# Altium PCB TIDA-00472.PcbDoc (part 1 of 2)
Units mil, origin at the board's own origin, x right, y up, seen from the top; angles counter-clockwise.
Board outline 3661.41 x 4133.85 mil, 2 copper layers (Top Layer, Bottom Layer), stack 62 mil thick; 187 components, 96 nets, 460 pads, 195 vias.
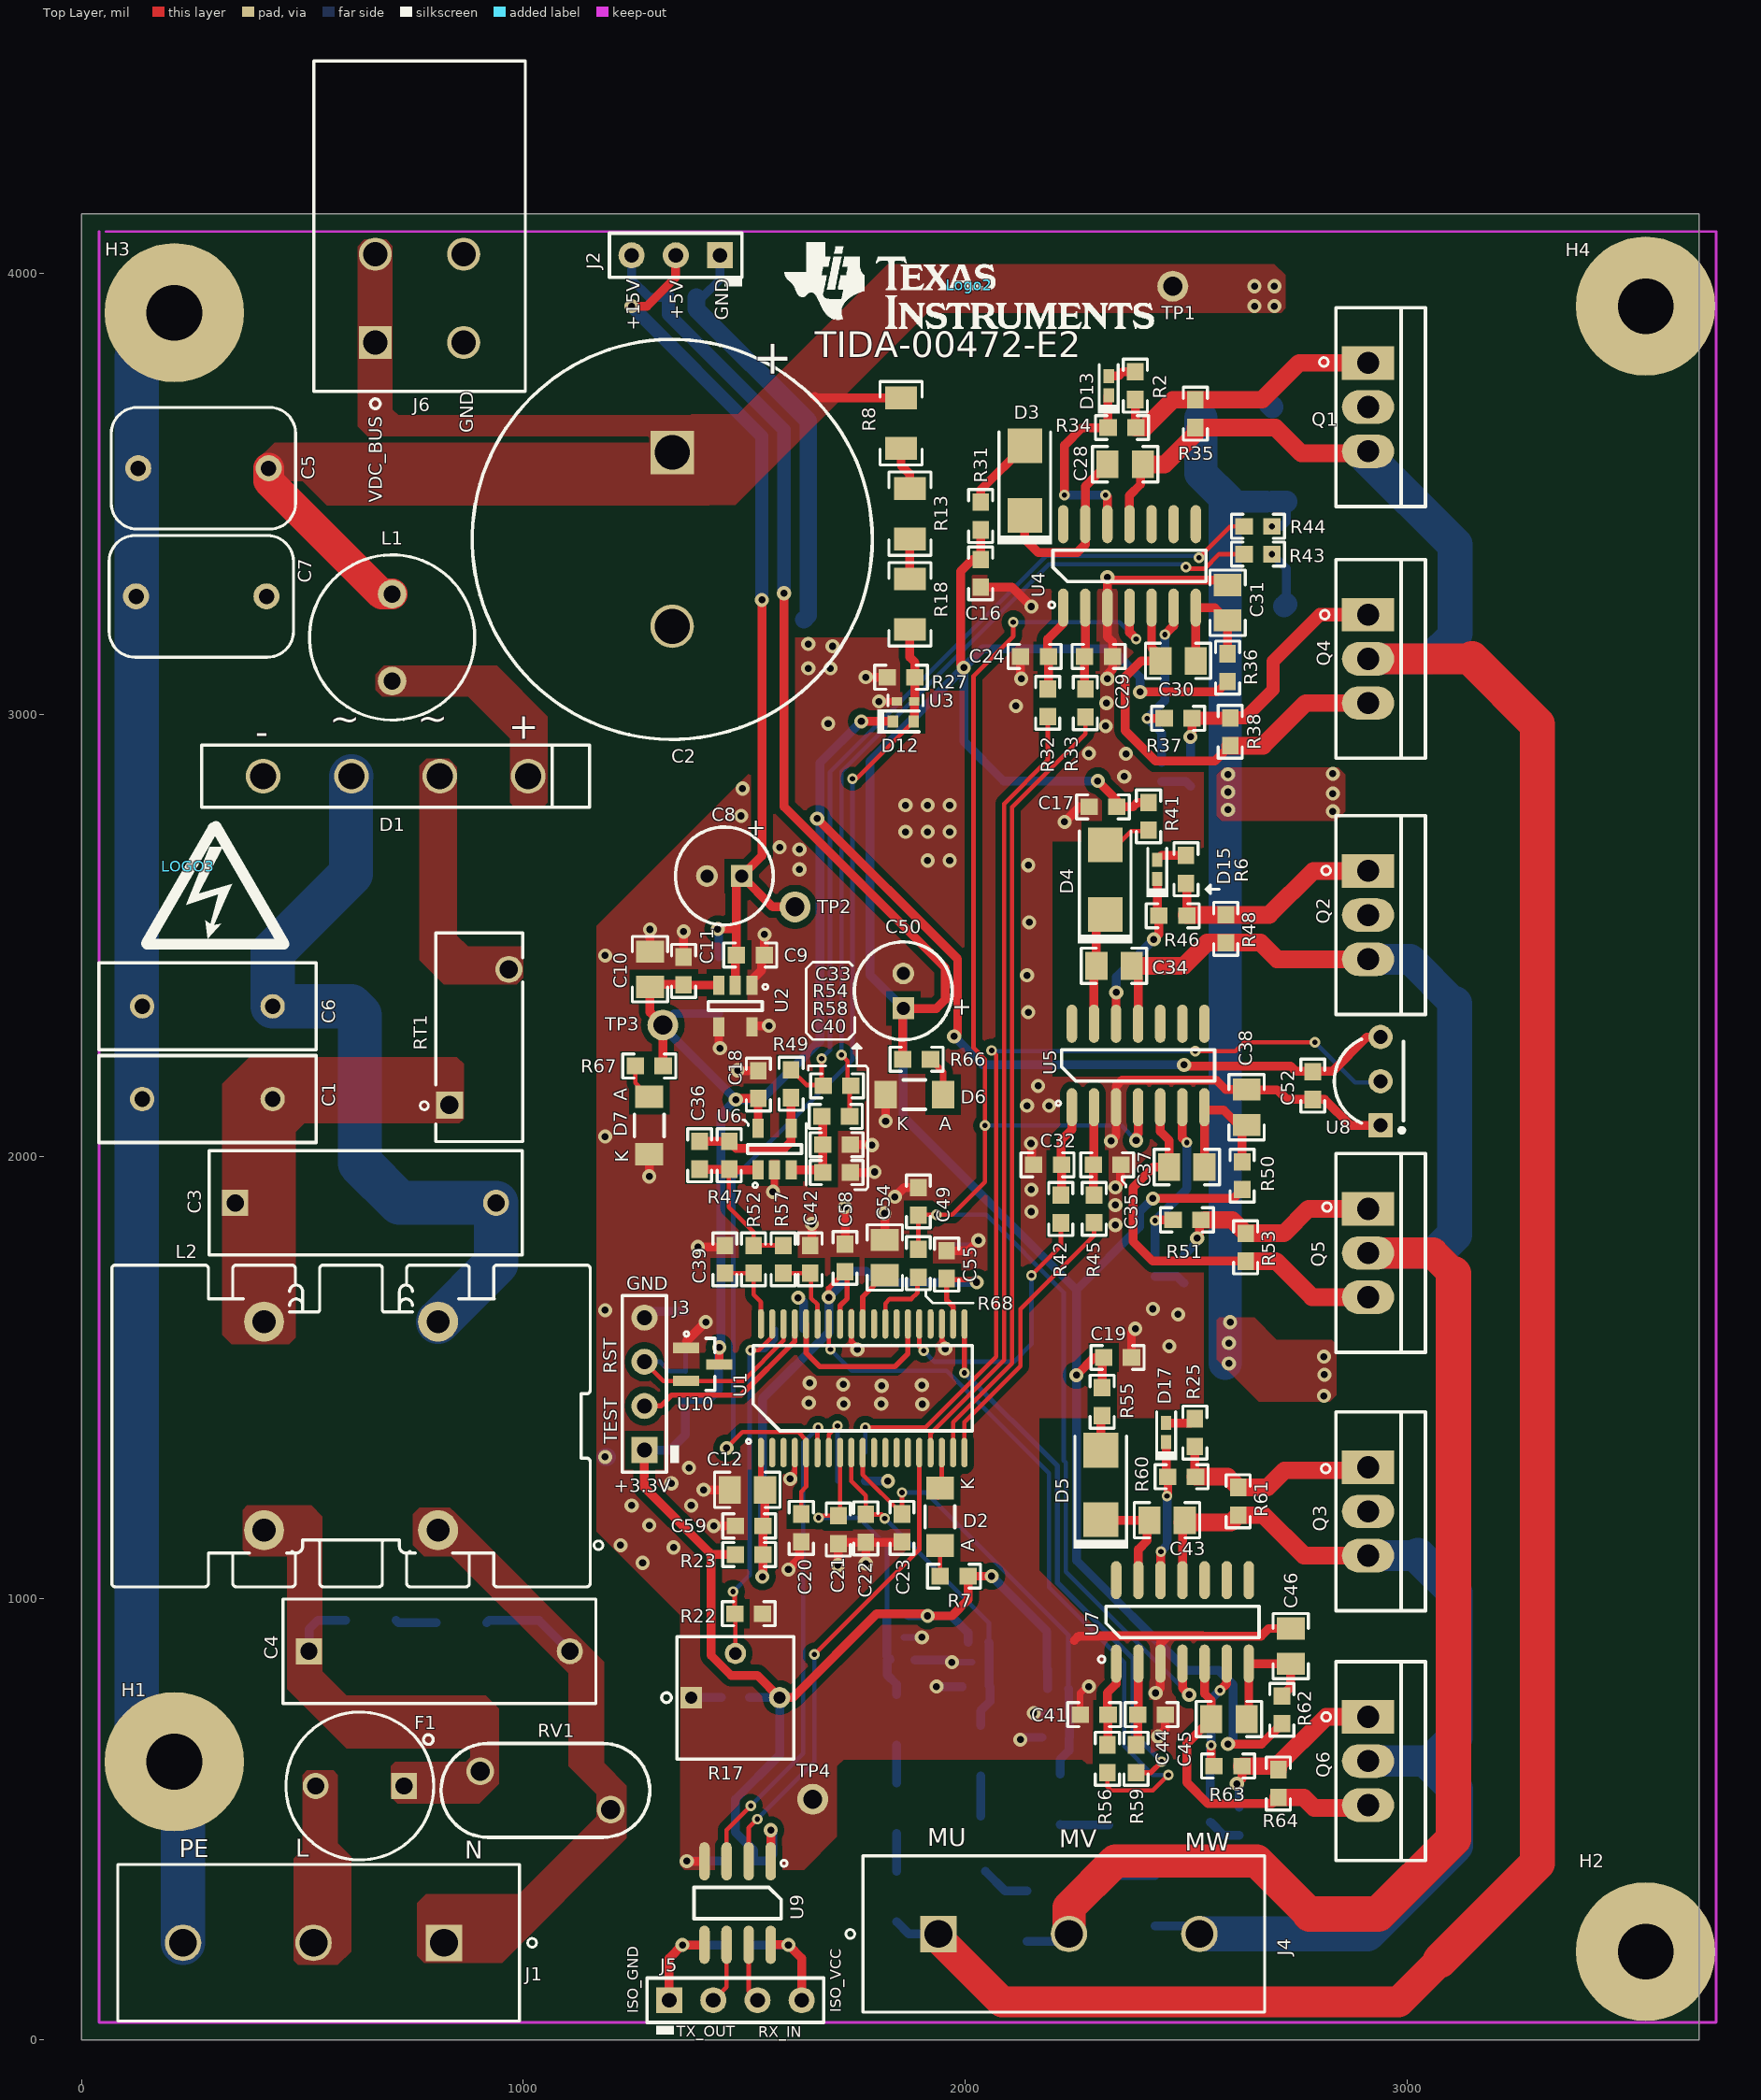
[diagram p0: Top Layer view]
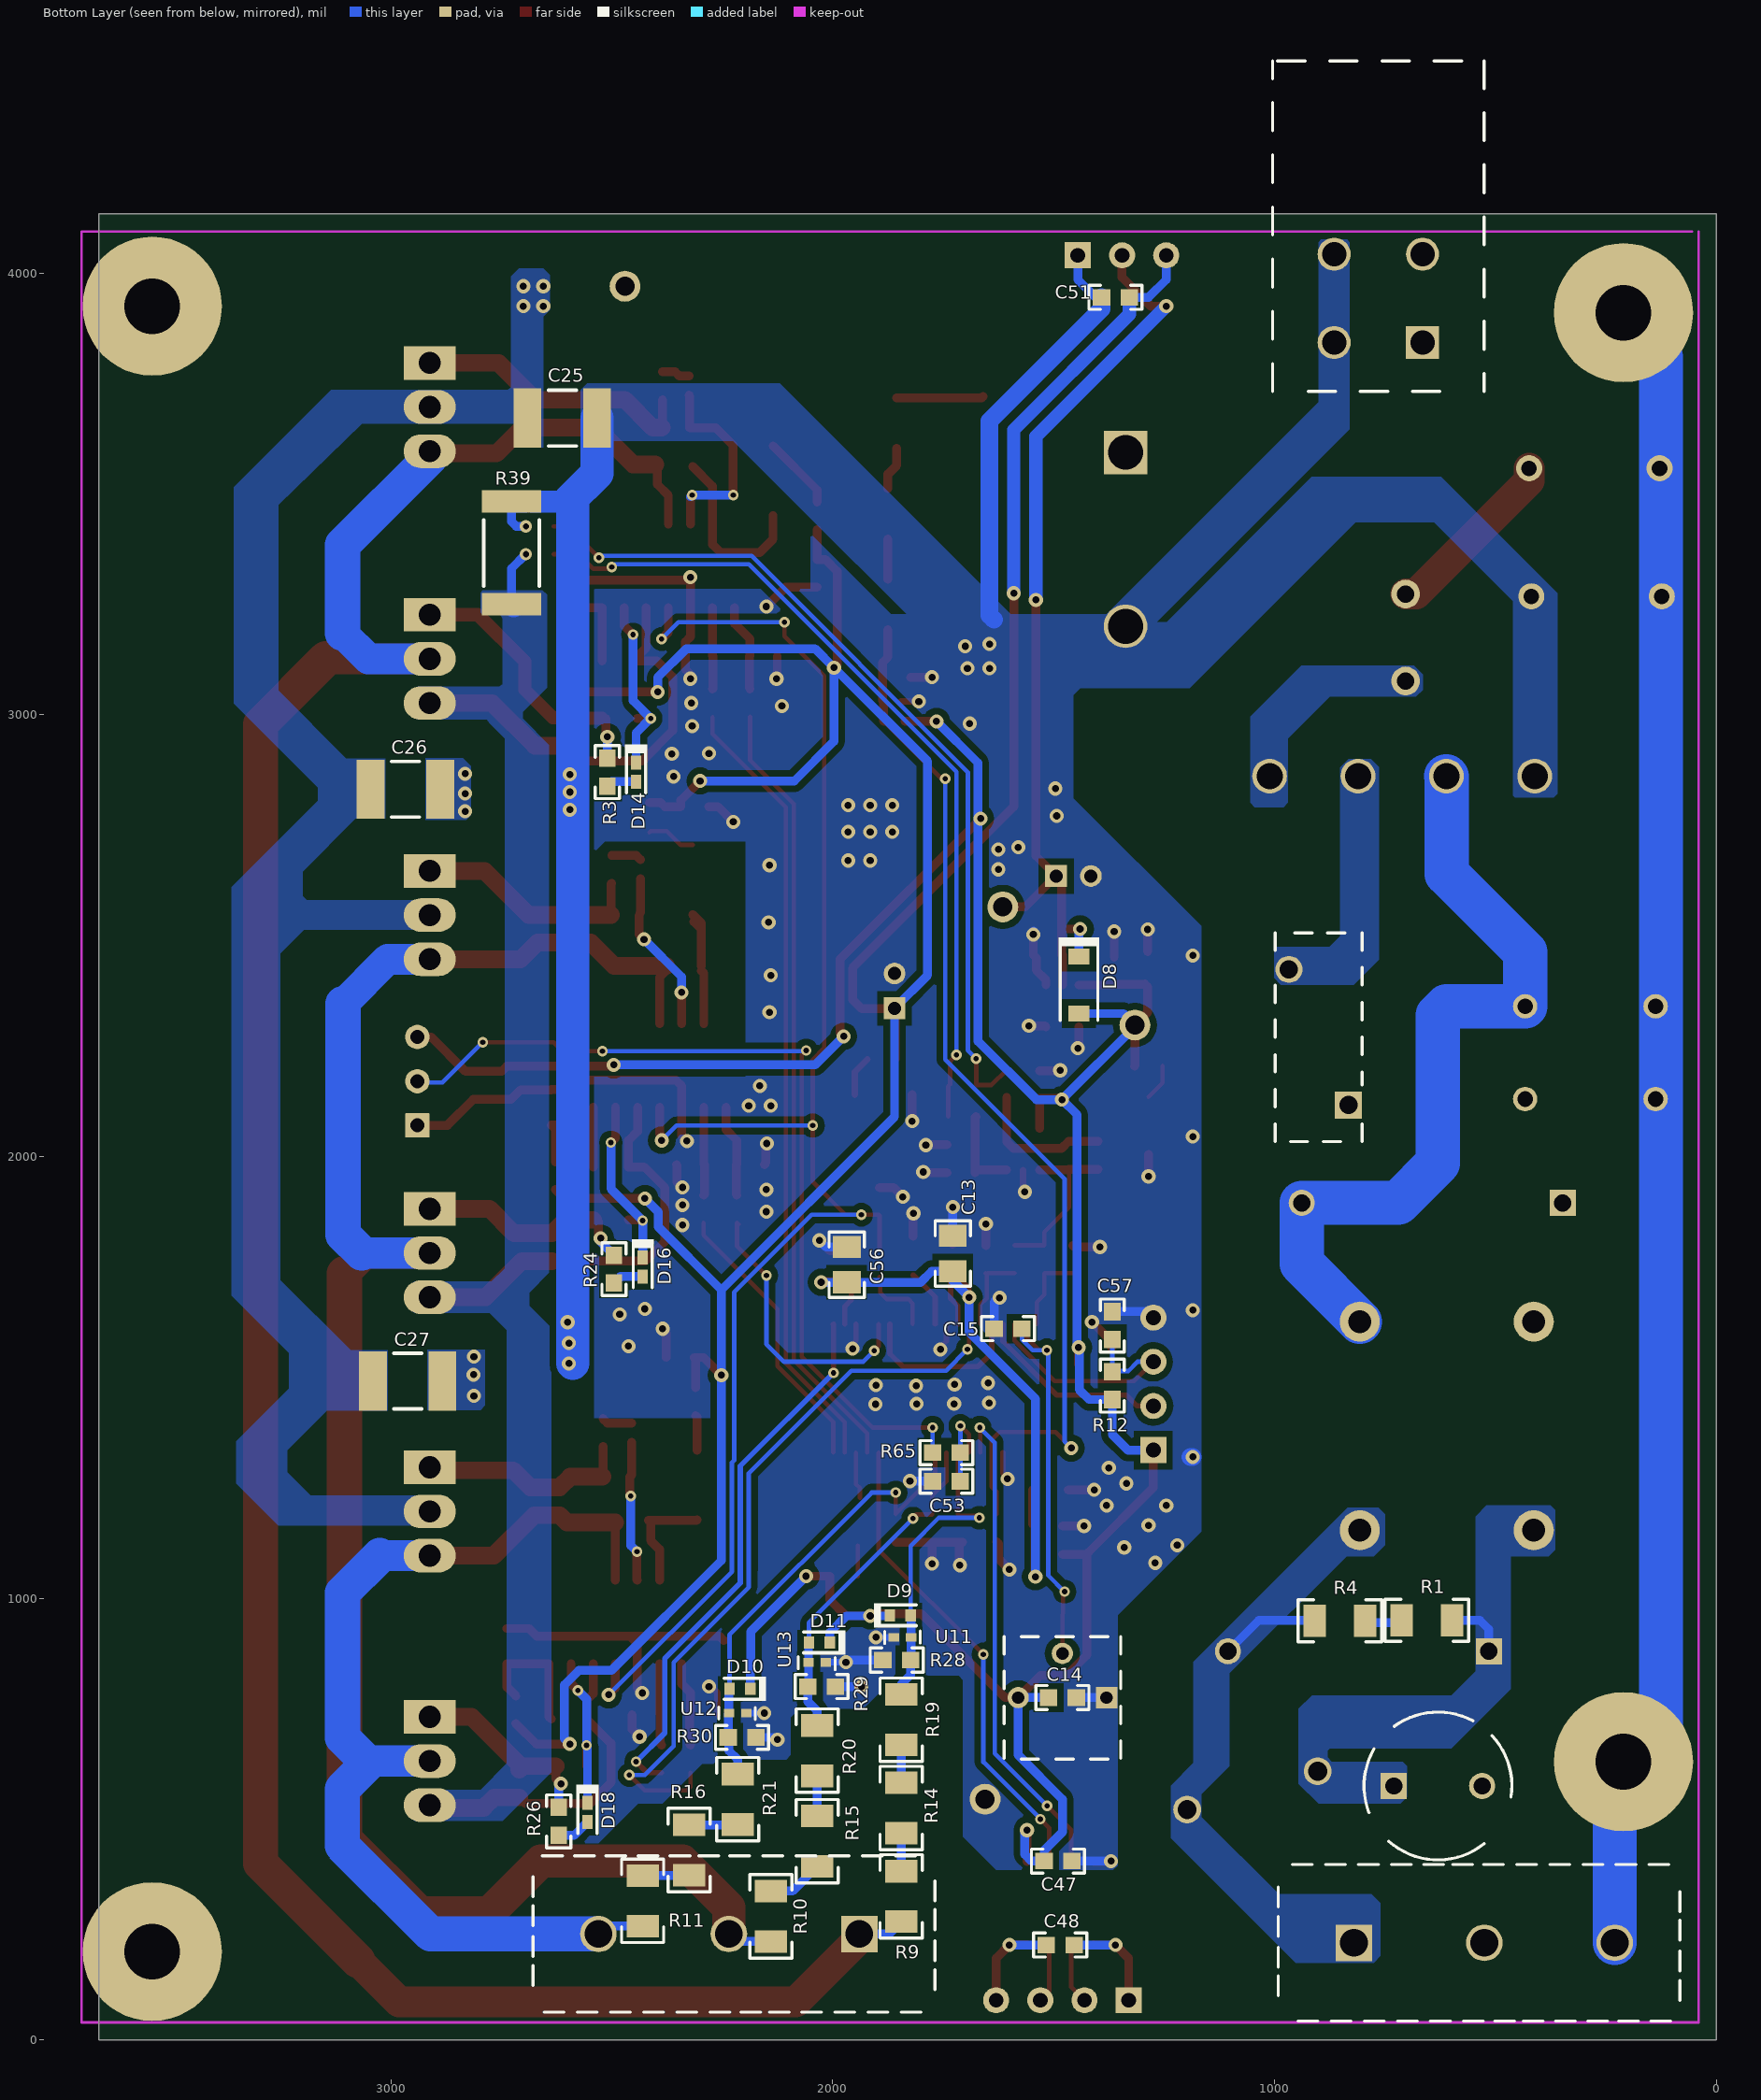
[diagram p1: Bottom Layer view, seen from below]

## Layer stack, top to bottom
Top Solder: solder mask 0.4, Solder Resist, Dk 3.5
Top Layer: signal copper 1.4
Dielectric1: core 59.2, FR-4, Dk 4.8
Bottom Layer: signal copper 1.4
Bottom Solder: solder mask 0.4, Solder Resist, Dk 3.5

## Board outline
0,0 3661.41,0 3661.41,4133.85 0,4133.85

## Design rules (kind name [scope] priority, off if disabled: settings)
AcuteAngle [All] p1: minimum=4.50000000000000E+0001 checktracksonly=FALSE
AssemblyTestPointUsage [All] p1: valid=2
Clearance Clearance_Boardedge_poly [OnCopper and InPolygon vs IsKeepOut] p1: gap=15
Clearance "Clearance_via_thr pin" [IsVia vs IsThruPin] p2: gap=8
Clearance Clearance_MTG_COPPER [InPadClass('MTG') vs InPolygon] p3: gap=40
Clearance "shape to all" [InPolygon] p4: gap=15
Clearance "Shape to Shape" [InPolygon vs InPolygon] p5: gap=25
Clearance "SMD to Via" [IsSMTPin vs IsVia] p6: gap=8
Clearance [All] p7: gap=8
DiffPairsRouting DiffPair_DiffPairsRouting [InDifferentialPair ('kan')] p1: maxlimit=10 minlimit=10 mostfreqgap=10 toplayer_minwidth=15 toplayer_maxwidth=15 toplayer_prefwidth=15 bottomlayer_minwidth=15 bottomlayer_maxwidth=15 bottomlayer_prefwidth=15 maxuncoupledlength=500
DiffPairsRouting DiffPair_DiffPairsRouting_1 [InDifferentialPair ('kan')] p2: maxlimit=10 minlimit=10 mostfreqgap=10 toplayer_minwidth=15 toplayer_maxwidth=15 toplayer_prefwidth=15 bottomlayer_minwidth=15 bottomlayer_maxwidth=15 bottomlayer_prefwidth=15 maxuncoupledlength=500
DiffPairsRouting [All] p3: maxlimit=100 minlimit=10 mostfreqgap=10 toplayer_minwidth=15 toplayer_maxwidth=15 toplayer_prefwidth=15 bottomlayer_minwidth=15 bottomlayer_maxwidth=15 bottomlayer_prefwidth=15 maxuncoupledlength=1000
FabricationTestPointUsage TestPointUsage [All] p1: valid=2 allowmultiple=FALSE
FabricationTestpoint Testpoint [All] p1: side=3 testpointundercomponent=TRUE minsize=40 maxsize=100 preferedsize=60 minholesize=0 maxholesize=40 preferedholesize=32 testpointgrid=1 allowsidetop=TRUE allowsidebottom=TRUE usegrid=TRUE gridtolerance=0.01
FanoutControl Fanout_LCC [IsLCC] p1: bgadir=Out bgaviamode=Centered fanoutstyle=Auto fanoutdirection=Alternating viagrid=1 // Fanout_LCC (Default Rule)
FanoutControl Fanout_BGA [IsBGA] p2: bgadir=Out bgaviamode=Centered fanoutstyle=Auto fanoutdirection=Alternating viagrid=1 // Fanout_BGA (Default Rule)
FanoutControl Fanout_Default [All] p4: bgadir=Out bgaviamode=Centered fanoutstyle=Auto fanoutdirection=Alternating viagrid=1 // Fanout_Default (Default Rule)
FanoutControl Fanout_Small [(CompPinCount < 5)] p5: bgadir=Out bgaviamode=Centered fanoutstyle=Auto fanoutdirection=OutThenIn viagrid=1 // Fanout_Small (Default Rule)
HoleSize [All] p1: absolutevalues=TRUE maxlimit=251 minlimit=7 maxpercent=80.000 minpercent=20.000
MatchedLengths DiffPair_MatchedLengths [InDifferentialPair ('kan')] p1: tolerance=1000 checknetsindiffpair=TRUE checkdiffpairvsdiffpair=TRUE checkothers=TRUE
MatchedLengths DiffPair_MatchedLengths_1 [InDifferentialPair ('kan')] p2: tolerance=1000 checknetsindiffpair=TRUE checkdiffpairvsdiffpair=TRUE checkothers=TRUE
MinimumAnnularRing [All] p1: minimumring=5
MinimumAnnularRing MinimumAnnularRing_ThermalPadVias [IsVia and InAnyComponent] p2: minimumring=5.91
MinimumSolderMaskSliver MinimumSolderMaskSliver_Logo [InComponentClass('Logo') vs InComponentClass('Logo')] p1: minsoldermaskwidth=0.7
MinimumSolderMaskSliver [All] p2: minsoldermaskwidth=3.94
PlaneClearance [All] p1: clearance=15
PlaneConnect [All] p1: planeconnectstyle=Direct reliefexpansion=10 reliefentries=4 reliefconductorwidth=10 reliefairgap=10
PolygonConnect [All] p1: connectstyle=Direct reliefconductorwidth=10 reliefentries=4 polygonreliefangle="90 Angle" airgapwidth=10
RoutingVias RoutingVias_power [InNetClass('POWER')] p1: holewidth=16 width=32 viastyle="Through Hole" minholewidth=7.87 minwidth=19.68 maxholewidth=16 maxwidth=32
RoutingVias ThermalPadVias [IsVia and InAnyComponent] p2: holewidth=8 width=20 viastyle="Through Hole" minholewidth=7.87 minwidth=19 maxholewidth=12 maxwidth=24
RoutingVias [All] p3: holewidth=12 width=24 viastyle="Through Hole" minholewidth=12 minwidth=24 maxholewidth=16 maxwidth=32
SMDToCorner [All] p1: distance=30000
SilkToSilkClearance [All] p1: silktosilkclearance=5
SilkToSolderMaskClearance SilkscreenOverComponentPads [IsPad] p1: minsilkscreentomaskgap=5 clearancetoexposedcopper=TRUE
SolderMaskExpansion [All] p1: expansion=3
UnpouredPolygon [All] p1: allowunpoured=FALSE
Width Width_power [InNetClass('pwr')] p1: maxlimit=200 minlimit=10 preferedwidth=20
Width [All] p2: maxlimit=100 minlimit=10 preferedwidth=20 checkconnectedcopper=TRUE
15 further rules are at their usual default settings.

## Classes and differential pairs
component class pg3-Main: C16 C17 C18 C19 C24 C25 C26 C27 C28 C29 C30 C31 C32 C33 C34 C35 C36 C37 C38 C39 C40 C41 C42 C43 C44 C45 C46 D3 D4 D5 D13 D14 D15 D16 D17 D18 J4 Q1 Q2 Q3 Q4 Q5 Q6 R2 R3 R6 R24 R25 R26 R31 R32 R33 R34 R35 R36 R37 R38 R39 R41 R42 R43 R44 R45 R46 R47 R48 R49 R50 R51 R52 R53 R54 R55 R56 R57 R58 R59 R60 R61 R62 R63 R64 U4 U5 U6 U7
component class Pg2-Main_1: C1 C2 C3 C4 C5 C6 C7 C8 C9 C10 C11 C12 C13 C14 C15 C20 C21 C22 C23 C47 C48 C49 C50 C51 C52 C53 C54 C55 C56 C57 C58 C59 D1 D2 D6 D7 D8 D9 D10 D11 D12 F1 J1 J2 J3 J5 J6 L1 L2 R1 R4 R7 R8 R9 R10 R11 R12 R13 R14 R15 R16 R17 R18 R19 R20 R21 R22 R23 R27 R28 R29 R30 R65 R66 R67 R68 RT1 RV1 TP1 TP2 TP3 TP4 U1 U2 U3 U8 U9 U10 U11 U12 U13
component class Pg4-Hardware: H1 H2 H3 H4 Logo2 ZZ1 ZZ2 ZZ3 ZZ4
component class AssemblyNote: ZZ1 ZZ2 ZZ3 ZZ4
component class Header: J2
component class "Mounting Holes": H1 H2 H3 H4
component class Logo: Logo2

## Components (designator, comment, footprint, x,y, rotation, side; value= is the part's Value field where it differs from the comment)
C1 "VY2472M49Y5US63V7" VY2_1250x500x1650 285,2130 r0 top
C2 "EET-ED2G181BA" CAPPR10-22x45 1337,3397 r270 top
C3 "B32922C3334M189" B32922_12mm 643,1895 r0 top
C4 "B32922C3334M189" B32922_12mm 810,880 r0 top
C5 "CS11-E2GA222MYNS" CAPRD750W60D1050H1450 276,3558 r180 top
C6 "VY2472M49Y5US63V7" VY2_1250x500x1650 285,2340 r180 top
C7 "CS11-E2GA222MYNS" CAPRD750W60D1050H1450 271,3268 r0 top
C8 "URZ1E220MDD1TD" RZ_500x900 1455,2635 r180 top
C9 "06033C104JAT2A" 0603 1513.8,2455.98 r0 top
C10 "0805YD106MAT2A" 0805_HV 1286.8,2423.98 r90 top
C11 "0603YC104JAT2A" 0603 1362.8,2419.98 r90 top
C12 "0805YD106MAT2A" 0805_HV 1507.08,1245.26 r180 top
C13 "0805YD106MAT2A" 0805_HV 1728.08,1780.26 r90 bottom
C14 "0603YC104JAT2A" 0603 1480,775 r180 bottom
C15 "0603YC104JAT2A" 0603 1603.08,1610.26 r0 bottom
C16 "C0603C104J3RAC" 0603 2035,3320 r270 top
C17 "C0603C104J3RAC" 0603 2312,2791.5 r180 top
C18 "0603YC104JAT2A" 0603 1532.08,2162.76 r90 top
C19 "C0603C104J3RAC" 0603 2345,1545 r0 top
C20 "06031C103KAT2A" 0603 1629.08,1159.26 r270 top
C21 "06031C103KAT2A" 0603 1713.08,1155.26 r270 top
C22 "06031C103KAT2A" 0603 1775.08,1158.26 r270 top
C23 "06031C103KAT2A" 0603 1857.08,1159.26 r270 top
C24 "06035A221FAT2A" 0603 2157,3131.94 r180 top
C25 "VJ1812Y104KXEAT5Z" 1812 2612,3671.5 r180 bottom
C26 "VJ1812Y104KXEAT5Z" 1812 2967,2831.5 r180 bottom
C27 "VJ1812Y104KXEAT5Z" 1812 2962,1491.5 r180 bottom
C28 "GRM21BR71E104KA01L" 0805_HV 2362,3566.94 r0 top
C29 "06035A221FAT2A" 0603 2302,3131.94 r0 top
C30 "GRM21BR71E105KA99L" 0805_HV 2482,3121.94 r0 top
C31 "GRM21BR71E105KA99L" 0805_HV 2594,3253.5 r90 top
C32 "06035A221FAT2A" 0603 2186.57,1981.07 r180 top
C33 "GRM188R61H102KA01D" 0603 1710,2160 r180 top
C34 "GRM21BR71E104KA01L" 0805_HV 2337,2431.5 r0 top
C35 "06035A221FAT2A" 0603 2321.57,1981.07 r0 top
C36 "GRM1885C1H221JA01D" 0603 1399.08,2002.76 r90 top
C37 "GRM21BR71E105KA99L" 0805_HV 2501.57,1976.07 r0 top
C38 "GRM21BR71E105KA99L" 0805_HV 2637,2111.5 r90 top
C39 "06035A470JAT2A" 0603 1456.08,1767.26 r270 top
C40 "GRM1885C1H221JA01D" 0603 1709.08,1963.76 r0 top
C41 "06035A221FAT2A" 0603 2292,736.5 r180 top
C42 "06035A470JAT2A" 0603 1649.08,1767.26 r270 top
C43 "GRM21BR71E104KA01L" 0805_HV 2457,1176.5 r0 top
C44 "06035A221FAT2A" 0603 2422,736.5 r0 top
C45 "GRM21BR71E105KA99L" 0805_HV 2597,726.5 r0 top
C46 "GRM21BR71E105KA99L" 0805_HV 2737,891.5 r90 top
C47 "06033C104KAT2A" 0603 1490,405 r0 bottom
C48 "06033C104KAT2A" 0603 1485,215 r0 bottom
C49 "06035A470JAT2A" 0603 1894.08,1898.26 r270 top
C50 "URZ1E220MDD1TD" RZ_500x900 1860,2375 r90 top
C51 "06033C104JAT2A" 0603 1360,3945 r0 bottom
C52 "0603YC104JAT2A" 0603 2787,2160.5 r90 top
C53 "0603YC104JAT2A" 0603 1742.49,1264.85 r0 bottom
C54 "C0805C474K4RACTU" 0805_HV 1818.08,1771.26 r90 top
C55 "0603YC104JAT2A" 0603 1958.08,1755.26 r90 top
C56 "0805YD106MAT2A" 0805_HV 1968.08,1755.26 r90 bottom
C57 "C0603C222K5RAC" 0603 1367.08,1617.26 r90 bottom
C58 "0603YC104JAT2A" 0603 1728.08,1770.26 r90 top
C59 "0603YC104JAT2A" 0603 1511.08,1163.76 r180 top
D1 "GBJ2510-BP" GBU 711,2861 r180 top
D2 "HBR1105W-TR" 1105W_Red 1943.08,1184.26 r90 top
D3 "US1M-13-F" SMA 2135,3530 r90 top
D4 "US1M-13-F" SMA 2317,2626.5 r90 top
D5 "US1M-13-F" SMA 2307,1256.5 r90 top
D6 "HBR1105W-TR" 1105W_Red 1885,2140 r180 top
D7 "HBR1105W-TR" 1105W_Red 1285,2070 r270 top
D8 "1N5819HW-7-F" SOD-123 1442.42,2388.07 r270 bottom
D9 "CDBP0130L-G" SOD-723 1847,961.5 r180 bottom
D10 "CDBP0130L-G" SOD-723 2210,795 r0 bottom
D11 "CDBP0130L-G" SOD-723 2030,900 r0 bottom
D12 "CDBP0130L-G" SOD-723 1860,2985 r0 top
D13 "SDM20U40-7-F" SOD-523 2325,3745 r90 top
D14 "SDM20U40-7-F" SOD-523 2445,2870 r270 bottom
D15 "SDM20U40-7-F" SOD-523 2435,2650 r90 top
D16 "SDM20U40-7-F" SOD-523 2430,1750 r270 bottom
D17 "SDM20U40-7-F" SOD-523 2455,1375 r90 top
D18 "SDM20U40-7-F" SOD-523 2555,515 r270 bottom
F1 "37321000410" FUSE_37321000430 630,575 r180 top
H1 "NY PMS 440 0025 PH" "NY PMS 440 0025 PH" 210,630 r0 top
H2 "NY PMS 440 0025 PH" "NY PMS 440 0025 PH" 3540.15,200 r0 top
H3 "NY PMS 440 0025 PH" "NY PMS 440 0025 PH" 210,3910 r0 top
H4 "NY PMS 440 0025 PH" "NY PMS 440 0025 PH" 3540.15,3925 r0 top
J1 "OSTVI034152" ONSHORE_OSTVI034152 525,220 r180 top
J2 "800-10-003-10-001000" Mill-Max_800-10-003-10-001000 1345,4040 r180 top
J3 "HEADER_1X4" Mill-Max_800-10-004-10-001000 1274.08,1485.26 r90 top
J4 "OSTVI034152" ONSHORE_OSTVI034152 2235,240 r0 top
J5 "HEADER_1X4" Mill-Max_800-10-004-10-001000 1480,90 r0 top
J6 "1757242" PHOENIX_1786404 765,4106 r180 top
L1 "13R103C" IND_1300R 703,3175 r90 top
L2 "744824310" IND_WE-CMB_L 610,1390 r180 top
Logo2 "Texas Instruments" TI_Stacked_Overlay_Small 2009.35,3971.73 r0 top
LOGO3 "DANGER HIGH VOLTAGE" IEC_HighVoltage_Medium 241,2656 r0 top
Q1 "FGP20N60UFDTU" TO-220AB 2912,3696.5 r270 top
Q2 "FGP20N60UFDTU" TO-220AB 2912,2546.5 r270 top
Q3 "FGP20N60UFDTU" TO-220AB 2912,1196.5 r270 top
Q4 "FGP20N60UFDTU" TO-220AB 2912,3126.5 r270 top
Q5 "FGP20N60UFDTU" TO-220AB 2912,1781.5 r270 top
Q6 "FGP20N60UFDTU" TO-220AB 2912,631.5 r270 top
R1 "CRCW1206499KFKEA" 1206 655,950 r180 bottom
R2 "CRCW06033R30JNEA" 0603 2385,3745 r270 top
R3 "CRCW06033R30JNEA" 0603 2510,2870 r90 bottom
R4 "CRCW1206499KFKEA" 1206 852,949 r180 bottom
R6 "CRCW06033R30JNEA" 0603 2500,2650 r270 top
R7 "CRCW060310K0FKEA" 0603 1975,1050 r180 top
R8 "RC1206FR-07499KL" 1206 1855,3660 r90 top
R9 "CRCW1206150KFKEA" 1206 1845,325 r270 bottom
R10 "CRCW1206150KFKEA" 1206 2140,280 r270 bottom
R11 "CRCW1206150KFKEA" 1206 2430,315 r270 bottom
R12 "CRCW060347K0JNEA" 0603 1367.08,1481.26 r270 bottom
R13 "RC1206FR-07499KL" 1206 1875,3455 r90 top
R14 "CRCW1206150KFKEA" 1206 1845,525 r270 bottom
R15 "CRCW1206150KFKEA" 1206 2035,450 r270 bottom
R16 "CRCW1206150KFKEA" 1206 2325,430 r270 bottom
R17 "3386P-1-203LF" TRIM_3362P 1480,775 r0 top
R18 "RC1206FR-07499KL" 1206 1875,3250 r90 top
R19 "CRCW1206150KFKEA" 1206 1845,725 r270 bottom
R20 "CRCW1206150KFKEA" 1206 2035,655 r270 bottom
R21 "CRCW1206150KFKEA" 1206 2215,545 r270 bottom
R22 "CRCW06031M00JNEA" 0603 1510,965 r180 top
R23 "RC0603FR-075R11L" 0603 1511.08,1098.76 r0 top
R24 "CRCW06033R30JNEA" 0603 2495,1745 r90 bottom
R25 "CRCW06033R30JNEA" 0603 2520,1375 r270 top
R26 "CRCW06033R30JNEA" 0603 2620,495 r90 bottom
R27 "CRCW060319K6FKEA" 0603 1855,3085 r0 top
R28 "CRCW06035K90FKEA" 0603 1855,860 r180 bottom
R29 "CRCW06035K90FKEA" 0603 2025,800 r0 bottom
R30 "CRCW06035K90FKEA" 0603 2205,685 r0 bottom
R31 "CRCW06033R30JNEA" 0603 2035,3450 r90 top
R32 "CRCW060351R1FKEA" 0603 2187,3026.94 r90 top
R33 "CRCW060351R1FKEA" 0603 2272,3026.5 r90 top
R34 "CRCW060310R0FKEAHP" 0603 2355,3650 r0 top
R35 "CRCW060320K0FKEA" 0603 2521,3681.5 r90 top
R36 "RC0603FR-075R11L" 0603 2594,3106.5 r90 top
R37 "CRCW060310R0FKEAHP" 0603 2482,2991.94 r0 top
R38 "CRCW060320K0FKEA" 0603 2600,2961.5 r90 top
R39 "CSRN2512FK50L0" 2512 2727,3366.5 r90 bottom
R41 "CRCW06033R30JNEA" 0603 2415,2770 r270 top
R42 "CRCW060351R1FKEA" 0603 2216.57,1881.07 r90 top
R43 "CRCW0603100RFKEA" 0603 2663,3363.5 r0 top
R44 "CRCW0603100RFKEA" 0603 2663,3426.5 r0 top
R45 "CRCW060351R1FKEA" 0603 2292,1881.5 r90 top
R46 "CRCW060310R0FKEAHP" 0603 2470,2545 r0 top
R47 "RG1608P-203-B-T5" 0603 1466.08,2002.76 r90 top
R48 "CRCW060320K0FKEA" 0603 2590,2515.5 r90 top
R49 "CRCW06031K00FKEA" 0603 1606.08,2164.76 r270 top
R50 "RC0603FR-075R11L" 0603 2627,1956.5 r90 top
R51 "CRCW060310R0FKEAHP" 0603 2502,1856.5 r0 top
R52 "CRCW060347R0JNEA" 0603 1521.08,1767.26 r270 top
R53 "CRCW060320K0FKEA" 0603 2635,1794.5 r90 top
R54 "CRCW06031K00FKEA" 0603 1707.08,2090.76 r180 top
R55 "CRCW06033R30JNEA" 0603 2310,1445 r270 top
R56 "CRCW060351R1FKEA" 0603 2322,636.5 r90 top
R57 "CRCW060347R0JNEA" 0603 1588.28,1767.26 r270 top
R58 "RG1608P-203-B-T5" 0603 1709.08,2026.76 r180 top
R59 "CRCW060351R1FKEA" 0603 2387,636.5 r90 top
R60 "CRCW060310R0FKEAHP" 0603 2490,1275 r0 top
R61 "CRCW060320K0FKEA" 0603 2618,1219.5 r90 top
R62 "RC0603FR-075R11L" 0603 2717,747.5 r90 top
R63 "CRCW060310R0FKEAHP" 0603 2595,620 r0 top
R64 "CRCW060320K0FKEA" 0603 2709,580.5 r90 top
R65 "CRCW06036K81FKEA" 0603 1742.49,1329.59 r0 bottom
R66 "CRCW060310K0FKEA" 0603 1890,2220 r0 top
R67 "CRCW060310K0FKEA" 0603 1285,2205 r180 top
R68 "CRCW060347R0JNEA" 0603 1894.08,1758.26 r270 top
RT1 "SL22 2R515" AMETHERM_SL12XXXXX 900,2270 r90 top
RV1 "S10K275E2" VAR_S10K275E2 1050,565 r180 top
TP1 "TP_K24A/M" HOLE-70X43 2470,3970 r0 top
TP2 "TP_K24A/M" HOLE-70X43 1615,2565 r90 top
TP3 "TP_K24A/M" HOLE-70X43 1315.8,2297.49 r270 top
TP4 "TP_K24A/M" HOLE-70X43 1655,545 r90 top
U1 "MSP430F5132IDA" DA0038A_N 1768.08,1475.26 r90 top
U2 "TLV70433DBVR" DBV0005A_N 1479.82,2340.82 r270 top
U3 "TPD1E10B06DPYR" DPY0002A 1865,3030 r180 top
U4 "UCC27714D14" D0014A_N 2372,3336.94 r90 top
U5 "UCC27714D14" D0014A_N 2391.57,2206.07 r90 top
U6 "OPA374AIDBVR" DBV0005A_N 1568.68,2016.52 r90 top
U7 "UCC27714D14" D0014A_N 2492,946.5 r90 top
U8 "LMT84LP" LP0003A 2940,2170.5 r0 top
U9 "ISO7421D" D0008A_N 1485,310 r270 top
U10 "TLV803MDBZR" DBZ0003A_N 1406.08,1529.26 r0 top
U11 "TPD1E10B06DPYR" DPY0002A 1842,911.5 r0 bottom
U12 "TPD1E10B06DPYR" DPY0002A 2215,740 r180 bottom
U13 "TPD1E10B06DPYR" DPY0002A 2035,855 r180 bottom
ZZ1 "This Assembly Note is for PCB labels only" AssemblyNoteLabel 100,6064 r0 top
ZZ2 "These assemblies are ESD sensitive, ESD precautions shall be observed." AssemblyNote 100,5979 r0 top (schematic designator ZZ3)
ZZ3 "These assemblies must be clean and free from flux and all contaminants. Use of no clean flux is not acceptable." AssemblyNote 100,5904 r0 top
ZZ4 "These assemblies must comply with workmanship standards IPC-A-610 Class 2, unless otherwise specified." AssemblyNote 100,5811 r90 top

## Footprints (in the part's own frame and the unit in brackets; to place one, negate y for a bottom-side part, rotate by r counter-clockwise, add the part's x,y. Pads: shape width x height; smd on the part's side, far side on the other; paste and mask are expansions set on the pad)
0603 [mm] "0603 from SM-752 data"
  rect 1x0.95 smd: 1(-0.8,0) 2(0.8,0)
  silkscreen extent -1.52,-0.69 1.52,0.69, body extent -0.87,-0.47 0.87,0.47, height 0.85
0805_HV [mil] "0805 with 30mil clearance between pads"
  rect 50x63 smd: 1(-40,0) 2(40,0)
  silkscreen extent -74,-40 74,40, body extent -43,-29 43,29, height 43
1105W_Red [mm] "Stanley Electric Co"
  rect 1.3x1.6 smd: 1(-1.65,0) 2(1.65,0)
  silkscreen extent -0.64,-0.85 0.64,0.85, body extent -1.65,-0.85 1.65,0.85, height 2.05
1206 [mm] "1206 from SM-752 data"
  rect 1.3x1.85 smd: 1(-1.45,0) 2(1.45,0)
  silkscreen extent -2.4,-1.21 2.4,1.21, body extent -1.7,-0.9 1.7,0.9, height 1.35
1812 [mm]
  rect 1.6x3.4 smd: 1(-2,0) 2(2,0)
  silkscreen extent -0.8,-1.6 0.8,1.6, body extent -2.4,-1.7 2.4,1.7, height 1.35
2512 [mm] "Chip Resistor, Body 6.3x3.2mm, IPC Medium Density"
  rect 1.3x3.4 smd: 1(-2.95,0) 2(2.95,0)
  silkscreen extent -1.9,-1.6 1.9,1.6, body extent -3.22,-1.67 3.22,1.67, height 0.71
AMETHERM_SL12XXXXX [mm] "INRUSH CURRENT LIMITER, 2 PIN, THRU"
  rect 1.554x1.554 / inner round 1.554 / far side rect 1.554x1.554 hole 1.054: 1(-3.9,1.71)
  round 1.554 hole 1.054: 2(3.9,-1.71)
  silkscreen extent -6,-2.5 6,2.5, body extent -6,-2.5 6,2.5, height 18.35
AssemblyNote [mil] "Assembly Note"
AssemblyNoteLabel [mil] "Assembly Note for PCB Labels"
B32922_12mm [mm] "Epcos film capacitors, 15mm spacing"
  rect 1.5x1.5 hole 0.991: 1(-7.5,0)
  round 1.5 hole 0.991: 2(7.5,0)
  silkscreen extent -9,-3 9,3, body extent -9,-3 9,3, height 12
CAPPR10-22x45 [mm] "Panasonic"
  rect 2.5x2.5 hole 2: 1(-5,0)
  round 2.5 hole 2: 2(5,0)
  silkscreen extent -11.5,-11.5 11.5,11.5, body extent -11.41,-11.48 11.47,11.48, height 47.01
CAPRD750W60D1050H1450 [mm] "TDK"
  round 1.5 hole 0.889: 1(-3.75,0) 2(3.75,0)
  silkscreen extent -5.3,-3.5 5.3,3.5, body extent -5.24,-3.5 5.24,3.5, height 14.46
D0008A_N [mm] "SOIC, 8-Leads, Body 4.9x3.9mm, Pitch 1.27mm, IPC Medium Density"
  oval 2.2x0.6 smd: 1(-2.4,1.905) 2(-2.4,0.635) 3(-2.4,-0.635) 4(-2.4,-1.905) 5(2.4,-1.905) 6(2.4,-0.635) 7(2.4,0.635) 8(2.4,1.905)
  silkscreen extent -0.9,-2.5 0.9,2.5, body extent -3,-2.45 3,2.45, height 1.63
D0014A_N [mm] "SOIC, 14-Leads, Body 8.7x3.9mm, Pitch 1.27mm, IPC Medium Density"
  oval 2.2x0.6 smd: 1(-2.4,3.81) 2(-2.4,2.54) 3(-2.4,1.27) 4(-2.4,0) 5(-2.4,-1.27) 6(-2.4,-2.54) 7(-2.4,-3.81) 8(2.4,-3.81) 9(2.4,-2.54) 10(2.4,-1.27) 11(2.4,0) 12(2.4,1.27) 13(2.4,2.54) 14(2.4,3.81)
  silkscreen extent -0.9,-4.4 0.9,4.4, body extent -3.02,-4.32 3.02,4.32, height 1.59
DA0038A_N [mm] "TSOP, 38-Leads, Body 12.6x6.2mm (max), Pitch 0.65mm, IPC Medium Density"
  oval 1.7x0.35 smd: 1(-3.7,5.85) 2(-3.7,5.2) 3(-3.7,4.55) 4(-3.7,3.9) 5(-3.7,3.25) 6(-3.7,2.6) 7(-3.7,1.95) 8(-3.7,1.3) 9(-3.7,0.65) 10(-3.7,0) 11(-3.7,-0.65) 12(-3.7,-1.3) 13(-3.7,-1.95) 14(-3.7,-2.6) 15(-3.7,-3.25) 16(-3.7,-3.9) 17(-3.7,-4.55) 18(-3.7,-5.2) 19(-3.7,-5.85) 20(3.7,-5.85) 21(3.7,-5.2) 22(3.7,-4.55) 23(3.7,-3.9) 24(3.7,-3.25) 25(3.7,-2.6) 26(3.7,-1.95) 27(3.7,-1.3) 28(3.7,-0.65) 29(3.7,0) 30(3.7,0.65) 31(3.7,1.3) 32(3.7,1.95) 33(3.7,2.6) 34(3.7,3.25) 35(3.7,3.9) 36(3.7,4.55) 37(3.7,5.2) 38(3.7,5.85)
  silkscreen extent -2.45,-6.3 2.45,6.3, body extent -4.17,-6.3 4.11,6.3, height 1.2
DBV0005A_N [mm] "SOT23, 5-Leads, Body 2.9x1.6mm, Pitch 0.95mm, Lead Span 2.8mm, IPC Medium Density"
  rect 1.1x0.65 smd: 1(-1.2,0.95) 2(-1.2,0) 3(-1.2,-0.95) 4(1.2,-0.95) 5(1.2,0.95)
  silkscreen extent -0.25,-1.55 0.25,1.55, body extent -1.42,-1.46 1.42,1.46, height 1.08
DBZ0003A_N [mm] "SOT23, 3-Leads, Body 2.9x1.3mm, Pitch 0.95mm, Lead Span 2.4mm, IPC Medium Density"
  rect 1.5x0.6 smd: 1(-0.95,0.95) 2(-0.95,-0.95) 3(0.95,0)
  silkscreen extent 0.2,-1.5 0.7,1.5, body extent -1.26,-1.46 1.26,1.46, height 0.96
DPY0002A [mm] "R-PX2SON-N2"
  rect 0.6x0.5 smd: 1(-0.5,0) 2(0.5,0)
  body extent -0.55,-0.35 0.55,0.35, height 0.4
FUSE_37321000430 [mm] "LITTELFUSE_373, TH-2P"
  rect 1.5x1.5 / inner round 1.5 / far side rect 1.5x1.5 hole 0.991: 1(-2.54,0)
  round 1.5 hole 0.991: 2(2.54,0)
  silkscreen extent -4.25,-4.25 4.25,4.25, body extent -4.26,-4.26 4.26,4.26, height 8
GBU [mm] "Comchip / Diodes Inc diode bridge"
  round 2 hole 1.5: 1(-7.62,0) 2(-2.54,0) 3(2.54,0) 4(7.62,0)
  silkscreen extent -11.15,-1.78 11.15,1.78, body extent -11.15,-1.76 11.15,1.8, height 21.55
HOLE-70X43 [mil]
  round 70 hole 43: 1(0,0)
IEC_HighVoltage_Medium [mil]
  silkscreen extent -94,-176 217,91
IND_1300R [mm] "Murata KMP_1300RC_A02"
  round 1.65 hole 0.991: 1(-2.5,0) 2(2.5,0)
  silkscreen extent -4.75,-4.75 4.75,4.75, body extent -4.76,-4.76 4.76,4.76, height 13.5
IND_WE-CMB_L [mm] "Wurth"
  round 2.3 hole 1.321: 2(-5,6) 4(5,6) 7(5,-6) 9(-5,-6)
  silkscreen extent -13.75,-9.25 13.75,9.25, body extent -13.75,-9.25 13.75,9.25, height 33.02
LP0003A [mm] "TO, Flat Index; 3 In-Line, Formed Axial Leads; Body Dia. 4.8mm; Leads 0.56 x 0.41 mm (max)"
  rrect7% 1.4x1.4 hole 0.8: 1(0,-2.54)
  round 1.4 hole 0.8: 2(0,0) 3(0,2.54)
  silkscreen extent -2.65,-2.95 1.35,2.41, body extent -2.35,-2.83 1.33,2.83, height 9.01
Mill-Max_800-10-003-10-001000 [mm] "Mill-Max"
  rect 1.5x1.5 hole 0.85: 1(-2.54,0)
  round 1.5 hole 0.85: 2(0,0) 3(2.54,0)
  silkscreen extent -3.81,-1.27 3.81,1.78, body extent -3.81,-1.27 3.81,1.27, height 8.13
Mill-Max_800-10-004-10-001000 [mm] "Mill-Max"
  rect 1.5x1.5 hole 0.85: 1(-3.81,0)
  round 1.5 hole 0.85: 2(-1.27,0) 3(1.27,0) 4(3.81,0)
  silkscreen extent -5.08,-1.98 5.08,1.27, body extent -5.08,-1.27 5.08,1.27, height 8.13
"NY PMS 440 0025 PH" [mm] "4-40 nylon screw and mounting hole"
  round 8 hole 3.2: 1(0,0)
  body extent -3.3,-3.3 3.3,3.3, height 2.69
ONSHORE_OSTVI034152 [mm] "TERMINAL BLOCK, 7.5MM PITCH,THRU-3PINS"
  rect 2.1x2.1 / inner round 2.1 / far side rect 2.1x2.1 hole 1.6: 1(-7.5,0)
  round 2.1 hole 1.6: 2(0,0) 3(7.5,0)
  silkscreen extent -12.83,-4.5 11.25,4.5, body extent -11.8,-4.5 11.3,4.5, height 13.5
PHOENIX_1786404 [mm] "TERM BLOCK, 2POS, R/A 5.08MM PITCH"
  rect 1.9x1.9 / inner round 1.9 / far side rect 1.9x1.9 hole 1.4: 1(2.54,6.69)
  round 1.9 hole 1.4: 1(2.54,1.61) 2(-2.54,6.69) 2(-2.54,1.61)
  silkscreen extent -6.08,-9.5 6.08,10.49, body extent -6.08,-9.5 6.08,9.5, height 10.2
RZ_500x900 [mm] "NICHICON"
  rect 1.25x1.25 hole 0.75: 1(-1,0)
  round 1.25 hole 0.75: 2(1,0)
  silkscreen extent -2.82,-2.82 2.81,2.82, body extent -2.73,-2.75 2.75,2.75, height 10.51
SMA [mm] "Molded Diode, 2-Leads, Body 4.3x2.6mm, IPC Medium Density, based on OnSemi component dimensions and land pattern"
  rect 2x2 smd: 1(-2,0) 2(2,0)
  silkscreen extent -3.66,-1.57 2.79,1.57, body extent -2.6,-1.3 2.6,1.3, height 2.42
SOD-123 [mm] "On Semi recommended land pattern"
  rect 0.915x1.22 smd: 1(-1.637,0) 2(1.637,0)
  silkscreen extent -2.74,-1.17 2.03,1.17, body extent -1.93,-0.9 1.93,0.9, height 1.35
SOD-523 [mm] "NXP Semiconductor recommended land pattern, nominal STEP model"
  rect 0.8x0.6 smd paste-0.05: 1(-0.55,0) 2(0.55,0)
  silkscreen extent -1.6,-0.64 1.2,0.63, body extent -0.8,-0.4 0.8,0.4, height 0.72
SOD-723 [mm] "SMD, 2-Leads, Body 1x0.6mm"
  rect 0.6x0.7 smd: 1(-0.6,0) 2(0.6,0)
  silkscreen extent -1.5,-0.7 0.9,0.7, body extent -0.75,-0.33 0.75,0.33, height 0.65
TI_Stacked_Overlay_Small [mil]
  silkscreen extent -418,-98 418,98
TO-220AB [mil] "Copied from Altium's version of TO3B"
  rect 76x118.11 hole 50: 1(-100,0)
  oval 76x118.11 hole 50: 2(0,0) 3(100,0)
  silkscreen extent -225,-110 225,130, body extent -221,-59 221,126, height 765
TRIM_3362P [mil] "POTENTIOMETER, 1/4\" SQUARE TRIMPOT, 3362, THRU-3P"
  rect 48.11x48.11 / inner round 48.11 / far side rect 48.11x48.11 hole 28.11: 1(-100,0)
  round 48.11 hole 28.11: 2(0,100) 3(100,0)
  silkscreen extent -167,-139 132,138, body extent -132,-139 132,138, height 185
VAR_S10K275E2 [mm] "EPCOS"
  round 1.6 hole 1.092: 1(-3.75,1.1) 2(3.75,-1.1)
  silkscreen extent -6,-2.7 6,2.7, body extent -5.98,-2.7 5.98,2.7, height 14.99
VY2_1250x500x1650 [mm] "TH, 2- Leads, Body 12.5x5mm, Pin Spacing 7.5mm"
  round 1.4 hole 0.889: 1(-3.75,0) 2(3.75,0)
  silkscreen extent -6.25,-2.5 6.25,2.5, body extent -6.2,-2.5 6.25,2.5, height 16.49

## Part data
C1 C6: "CAP, CERM, 4700 pF, 440 V, +/- 20%, Y5U, TH, 12.5x5mm"
C2: "CAP, AL, 180 µF, 400 V, +/- 20%, 0.737 ohm, TH"
C3 C4: library part BFC233620154, "CAP FILM 0.33UF 630VDC RADIAL"
C5 C7: "CAP, CERM, 2200 pF, 250 V, +/- 20%, E, Radial Disc D10.5x7mm"
C8 C50: "CAP, AL, 22uF, 25V, +/-20%, TH"
C9 C51: "CAP, CERM, 0.1uF, 25V, +/-5%, X7R, 0603"
C10 C12 C13 C56: "CAP, CERM, 10uF, 16V, +/-20%, X5R, 0805"
C11 C14 C15 C18 C52 C53: "CAP, CERM, 0.1uF, 16V, +/-5%, X7R, 0603"
C16 C17 C19: "CAP, CERM, 0.1 µF, 25 V, +/- 5%, X7R, 0603"
C20 C21 C22 C23: "CAP, CERM, 0.01uF, 100V, +/-10%, X7R, 0603"
C24 C29 C32 C35 C41 C44: "CAP, CERM, 220 pF, 50 V, +/- 1%, C0G/NP0, 0603"
C25 C26 C27: "CAP, CERM, 0.1 µF, 500 V, +/- 10%, X7R, 1812"
C28 C34 C43: "CAP, CERM, 0.1 µF, 25 V, +/- 10%, X7R, 0805"
C30 C31 C37 C38 C45 C46: "CAP, CERM, 1uF, 25V, +/-10%, X7R, 0805"
C33: "CAP, CERM, 1000 pF, 50 V, +/- 10%, X5R, 0603"
C36 C40: "CAP, CERM, 220 pF, 50 V, +/- 5%, C0G/NP0, 0603"
C39 C42 C49: "CAP, CERM, 47 pF, 50 V, +/- 5%, C0G/NP0, 0603"
C47 C48: "CAP, CERM, 0.1 µF, 25 V, +/- 10%, X7R, 0603"
C54: "CAP, CERM, 0.47 µF, 16 V, +/- 10%, X7R, 0805"
C55 C58 C59: "CAP, CERM, 0.1 µF, 16 V, +/- 5%, X7R, 0603"
C57: "CAP, CERM, 2200 pF, 50 V, +/- 10%, X7R, 0603"
D1: library part GBJ2506-BP, "RECT BRIDGE GPP 25A 1000V GBJ"
D2 D6 D7: "LED, Red, SMD"
D3 D4 D5: "Diode, Ultrafast, 1000V, 1A, SMA"
D8: "Diode, Schottky, 40 V, 1 A, SOD-123"
D9 D10 D11 D12: "Diode, Schottky, 30 V, 0.1 A, SOD-723"
D13 D14 D15 D16 D17 D18: "Diode, Schottky, 40 V, 0.25 A, SOD-523"
F1: library part 0216008.MXESPP, "FUSE BOARD MNT 10A 250VAC RADIAL"
H1 H2 H3 H4: "MACHINE SCREW PAN SLOTTED M3"
J1 J4: "TERMINAL BLOCK 7.50MM 3POS PCB, TH"
J2: "Header, 100mil, 3x1, TH"
J3 J5: "Header, Male 4-pin, 100mil spacing,"
J6: "Header (Shrouded), 5.08 mm, 2x1, Tin, R/A, TH"
L1: "Inductor, Drum Core, Ferrite, 10uH, 3A, 0.031 ohm, TH"
L2: "Coupled inductor, 10 mH, 3 A, 0.105 ohm, +/- 30%, TH"
Logo2: library part TI_Logo, "Texas Instrument Corporate Signature"
LOGO3: library part IEC_HighVoltage, "IEC 61010-1 High Voltage Warning"
Q1 Q2 Q3 Q4 Q5 Q6: library part STGP14NC60KD, "IC, IGBT, 600V, 25A, 80W, TO-220"
R1 R4: "RES, 499k ohm, 1%, 0.25W, 1206"
R2 R3 R6 R24 R25 R26 R31 R41 R55: "RES, 3.3, 5%, 0.1 W, 0603"
R7 R66 R67: "RES, 10.0 k, 1%, 0.1 W, 0603"
R8 R13 R18: "RES, 499 k, 1%, 0.25 W, 1206"
R9 R10 R11 R14 R15 R16 R19 R20 R21: "RES, 150k ohm, 1%, 0.25W, 1206"
R12: "RES, 47k ohm, 5%, 0.1W, 0603"
R17: "TRIMMER, 20k ohm, 0.5W, TH"
R22: "RES, 1.0Meg ohm, 5%, 0.1W, 0603"
R23 R36 R50 R62: "RES, 5.11, 1%, 0.1 W, 0603"
R27: "RES, 19.6 k, 1%, 0.1 W, 0603"
R28 R29 R30: "RES, 5.90 k, 1%, 0.1 W, 0603"
R32 R33 R42 R45 R56 R59: "RES, 51.1, 1%, 0.1 W, 0603"
R34 R37 R46 R51 R60 R63: "RES, 10.0, 1%, 0.25 W, 0603"
R35 R38 R48 R53 R61 R64: "RES, 20.0k ohm, 1%, 0.1W, 0603"
R39: "RES, 0.05, 1%, 2 W, 2512"
R43 R44: "RES, 100, 1%, 0.1 W, 0603"
R47 R58: "RES, 20.0 k, 0.1%, 0.1 W, 0603"
R49 R54: "RES, 1.00 k, 1%, 0.1 W, 0603"
R52 R57 R68: "RES, 47, 5%, 0.1 W, 0603"
R65: "RES, 6.81 k, 1%, 0.1 W, 0603"
RT1: library part SL155R007, "CURRENT LIMITR INRSH 2.5 OHM 15A"
RV1: "Varistor 275V RMS 10MM Radial, TH"
TP1 TP2 TP3 TP4: "Pin, Thru Hole, Tin Plate, for 0.062 PCB's"
U1: "25 MHz Mixed Signal Microcontroller with 8 KB Flash, 1024 B SRAM and 29 GPIOs, -40 to 85 degC, 38-pin SOP (DA), Green (RoHS & no Sb/Br)"
U2: "Single Output LDO, 150 mA, Fixed 3.3 V Output, 2.5 to 24 V Input, with Ultra-Low IQ, 5-pin SOT-23 (DBV), -40 to 125 degC, Green (RoHS & no Sb/Br)"
U3 U11 U12 U13: "ESD in 0402 Package with 10 pF Capacitance and 6 V Breakdown, 1 Channel, -40 to +125 degC, 2-pin X2SON (DPY), Green (RoHS & no Sb/Br)"
U4 U5 U7: "High-Speed Low-side Gate Driver Device, D0014A"
U6: "6.5 MHz, 585 uA, Rail-to-Rail I/O CMOS Operational Amplifier, 2.3 to 5.5 V, -40 to 125 degC, 5-pin SOT23 (DBV0005A), Green (RoHS & no Sb/Br)"
U8: "IC, TEMP SENSOR PREC ANLG, TO-92, ROHS"
U9: "1 Mbps Dual Channels, 1 / 1, Digital Isolator, 3.3 V / 5 V, -40 to +105 degC, 8-pin SOIC (D), Green (RoHS & no Sb/Br)"
U10: "3-Pin Voltage Supervisors with Active-Low, Open-Drain Reset, DBZ0003A"
ZZ1: library part AssemblyNoteLabel
ZZ2 ZZ3 ZZ4: library part AssemblyNote

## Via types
v1: diameter 32, hole 16, Top Layer to Bottom Layer, tented both sides, 154 vias
v2: diameter 24, hole 12, Top Layer to Bottom Layer, tented both sides, 39 vias
v3: diameter 28, hole 14, Top Layer to Bottom Layer, tented bottom, 2 vias

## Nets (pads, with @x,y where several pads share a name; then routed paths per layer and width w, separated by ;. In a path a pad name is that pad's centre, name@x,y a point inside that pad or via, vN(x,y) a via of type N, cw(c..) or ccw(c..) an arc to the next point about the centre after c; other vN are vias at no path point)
+3.3VD: C10.1 C11.1 C14.1 C18.1 C47.2 C52.2 D8.2 D9.1 D10.1 D11.1 D12.1 J3.1 R7.1 R12.2 R17.3 R23.1 R67.1 TP3.1 U2.3 U6.5 U8.3 U9.1 U10.3 | length 7116.1
  Top Layer w20: J3.1@1274.08,1335.26 1274.08,1250.92 1420.54,1104.46 ; C10.1@1286.8,2383.98 1286.8,2326.49 TP3.1@1315.8,2297.49 1315.8,2205.7 R67.1@1316.5,2205 ; C10.1@1293.8,2390.98 1295.45,2389.33 1361.54,2389.33 C11.1@1362.8,2388.07 ; C11.1@1362.8,2388.49 C11.1@1362.8,2388.07 ; U2.3@1442.42,2388.07 C11.1@1362.8,2388.07 ; U10.3@1443.48,1529.26 v1(1443.48,1567.67) ; R23.1@1479.58,1098.76 1425,1098.76 1425,870.53 1470.53,825 1530,825 R17.3@1580,775 1610,775 1800,965 1910,965 v1(1915,960) 1970,960 2006.5,996.5 R7.1@2006.5,1050 v1(2060,1050) ; v1(1481.08,2128.76) 1483.08,2128.76 1485.58,2131.26 C18.1@1532.08,2131.26 1531.27,2130.46 U6.5@1531.27,2063.76 ; U9.1@1560,404.49 v1(1560,475) ; v1(1665,2765) 1983,2447 1983,2280.08 v1(1975,2272.08) ; v1(1765,2985) D12.1@1836.38,2985 ; v1(2495.43,2207.5) 2498.43,2204.5 2737,2204.5 2749,2192.5 2831,2192.5 2909,2270.5 U8.3@2940,2270.5
  Bottom Layer w20: J3.1@1274.08,1335.26 1332.08,1335.26 1367.08,1370.26 R12.2@1367.08,1449.77 1419.58,1449.77 1442.08,1472.26 1442.08,1566.26 v1(1443.48,1567.67) 1447.08,1571.26 1447.08,2094.76 v1(1481.08,2128.76) ; D8.2@1442.42,2323.6 1341.91,2323.6 TP3.1@1315.8,2297.49 1315.8,2294.04 v1(1481.08,2128.76) ; C14.1@1511.5,775 R17.3@1580,775 1580,645 1480,545 1480,470.58 1521.5,429.08 C47.2@1521.5,405 1550,405 1565,420 1565,470 v1(1560,475) ; v1(1665,2765) v1@1671.08,2765 ; v1(1765,2985) 1671.08,2891.08 v1@1671.08,2765 ; D9.1@1870.62,961.5 1872.13,960 v1(1915,960) 1968.78,960 2006.38,922.4 D11.1@2006.38,900 ; v1(1975,2272.08) 2039.57,2207.5 v1(2495.43,2207.5) ; v1(2060,1050) 2185,925 2185,840 2186.38,838.62 D10.1@2186.38,795 ; v1(1481.08,2128.76) 1538.76,2128.76 1671.08,2261.08 v1@1671.08,2765
+5V: C8.1 C9.1 D8.1 J2.2 TP2.1 U2.2 | length 2116.2
  Top Layer w20: v1(1245,3925) 1280,3925 1345,3990 J2.2@1345,4040 ; v1(1440,2515) 1482.3,2515 ; U2.2@1479.82,2388.07 C9.1@1479.8,2455.98 ; C9.1@1482.3,2455.98 1482.3,2515 ; v1(1540,3260) 1540,2680.63 C8.1@1494.37,2635 ; TP2.1@1615,2565 1564.37,2565 C8.1@1494.37,2635 ; 1482.3,2515 1482.3,2622.93 C8.1@1494.37,2635
  Bottom Layer w20: v1(1440,2515) 1442.42,2512.58 D8.1@1442.42,2452.54 ; C8.1@1494.37,2635 C8.1@1495,2634.37
  Bottom Layer w30: v1(1245,3925) 1540,3630 v1(1540,3260)
+15V: C16.1 C17.1 C19.1 C50.1 C51.1 J2.3 R31.1 R36.1 R41.1 R50.1 R55.1 R62.1 R66.1 | length 7603.6
  Top Layer w20: v1(1590,3275) 1590,2791.92 1955,2426.92 1955,2355 1935,2335 1860.63,2335 C50.1@1860,2335.63 1858.5,2334.13 R66.1@1858.5,2220 ; v1(1997,3106.5) 1989.5,3114.01 1989.5,3324.5 2016.5,3351.5 C16.1@2035,3351.5 R31.1@2035,3418.5 ; v1(2252,1505) 2292,1545 C19.1@2313.5,1545 2310,1541.5 R55.1@2310,1476.5 ; v1(2300,2850) 2343.5,2806.5 C17.1@2343.5,2791.5 2380,2791.5 2389.99,2801.5 R41.1@2415,2801.5 ; v1(2396,3051.5) 2406.44,3051.5 2406.72,3051.78 2407,3051.5 2570.5,3051.5 R36.1@2594,3075.01 ; v1(2425,1905) 2606.99,1905 R50.1@2627,1925.01 ; v1(2595,670) 2670.99,670 R62.1@2717,716.01
  Bottom Layer w20: J2.3@1245,4040 1245,3985 1285,3945 C51.1@1328.5,3945 ; v1(2300,2850) 2087,2850 1997,2940 v1(1997,3106.5) ; v1(2396,3051.5) 2396,3084.5 2331,3149.5 2040,3149.5 v1(1997,3106.5) ; v1(2425,1905) 2395,1875 2395,1841 2252,1698 ; v1(2595,670) 2607,682 2607,803.93 2574.43,836.5 2501,836.5 2252,1085.5 v1(2252,1505) 2252,1698 ; v1(1997,3106.5) 1785,2894.5 1785,2410.63 C50.1@1860,2335.63 1860,2090 2252,1698
  Bottom Layer w30: C51.1@1328.5,3945 1328.5,3906.5 1590,3645 v1(1590,3275)
+VDC: C2.1 C5.1 C25.1 C26.1 C27.1 J6.1 L1.2 Q1.2 Q2.2 Q3.2 R8.2 TP1.1 | length 617.3
  Top Layer w20: 1660,3720 1662.91,3717.09 R8.2@1855,3717.09
  Top Layer w70: C5.1@423.64,3558 423.64,3529.36 679.57,3273.43 L1.2@703,3273.43
  Bottom Layer w50: C25.1@2690.74,3701.5 C25.1@2695.74,3696.5
  other v1: 2655,3925 2700,3925 2655,3970 2700,3970
AGND: C2.2 C7.2 C8.2 C9.2 C10.2 C11.2 C12.2 C13.2 C14.2 C15.2 C16.2 C17.2 C18.2 C19.2 C20.2 C21.2 C22.2 C23.2 C24.2 C25.2 C26.2 C27.2 C29.2 C31.2 C32.2 C35.2 C38.2 C39.1 C40.2 C41.2 C42.1 C44.2 C46.2 C47.1 C49.1 C50.2 C51.2 C52.1 C53.2 C54.2 C55.2 C56.2 C57.2 C58.2 C59.2 D1.4 D6.2 D7.2 J2.1 J3.4 J6.2 R17.1 R22.1 R27.1 R28.1 R29.1 R30.1 R39.2 R44.2 R58.1 TP4.1 U1.4 U1.22 U1.30 U2.1 U2.4 U2.5 U3.2 U4.3 U5.3 U6.2 U7.3 U8.1 U9.4 U10.1 U11.2 U12.2 U13.2 | length 8531.6
  Top Layer w12: v1(1604.08,1270.26) 1604.08,1273.26 1614.53,1283.72 U1.4@1614.53,1329.59 ; U1.30@1742.49,1620.93 1742.49,1581.85 1756.08,1568.26 v1(1756.08,1563.26) ; U1.22@1947.21,1620.93 1947.21,1583.13 1955,1575.34 v1(1955,1565)
  Top Layer w15: v1(1565,1920) 1568.68,1923.68 U6.2@1568.68,1969.27 ; v1(1805,3030) U3.2@1845.32,3030 ; v1(2155,740) v1@2160,740 ; C41.2@2260.5,736.5 2260.5,785.5 2275,800 v1(2280,800)
  Top Layer w20: C7.2@418.64,3268 C7.2@426,3260.64 ; v1(1285,1955) D7.2@1285,2005.04 ; C10.2@1286.8,2463.98 v1(1286.8,2513.98) ; C11.2@1362.8,2451.48 v1(1362.8,2509.12) ; U10.1@1368.68,1566.67 1368.68,1580.86 v1(1413.08,1625.26) ; v1(1370,405) 1380,405 1380.51,404.49 U9.4@1410,404.49 ; v1(1395.08,1795.26) 1452.58,1795.26 C39.1@1456.08,1798.76 ; v1(1408.08,1245.26) C12.2@1467.08,1245.26 ; v1(1431.08,1163.76) C59.2@1479.58,1163.76 ; U2.4@1442.42,2293.58 1442.42,2252.58 1445,2250 v1(1445,2245) ; v1(1485,2195) 1485.74,2194.26 C18.2@1532.08,2194.26 ; U2.5@1517.23,2293.58 1519.63,2295.98 v1(1555.8,2295.98) ; U2.1@1517.23,2388.07 1517.23,2399.41 1538.8,2420.98 1538.8,2449.49 C9.2@1545.3,2455.98 1545.8,2456.49 v1(1545.8,2502.49) ; v1(1600,1065) 1625.08,1090.08 1625.08,1123.77 C20.2@1629.08,1127.77 ; v1(1653.08,1847.26) 1654.08,1846.26 1654.08,1844.26 1653.28,1843.46 C42.1@1653.28,1798.76 ; C21.2@1706.08,1126.77 C22.2@1775.08,1126.77 ; v1(1712.08,1074.76) 1713.08,1075.76 C21.2@1713.08,1123.77 ; C58.2@1728.08,1801.76 v1(1728.08,1885.26) ; C40.2@1740.57,1963.76 1793.76,1963.76 v1(1795,1965) ; R58.1@1740.57,2026.76 1788.24,2026.76 v1(1789.12,2025.88) ; v1(1775,3085) R27.1@1823.5,3085 ; v1(1775.08,1078.26) 1774.08,1079.26 1774.08,1081.26 1775.08,1082.26 C22.2@1775.08,1126.77 ; v1(1817.08,1871.26) 1817.08,1869.26 1818.08,1868.26 C54.2@1818.08,1819.26 ; v1(1820,2080) v1(1820,2080) D6.2@1820.04,2140 ; v1(1841.08,1908.76) 1862.08,1929.76 C49.1@1894.08,1929.76 ; C23.2@1857.08,1127.77 1856.08,1126.77 C22.2@1775.08,1126.77 ; C55.2@1958.08,1786.76 2006.76,1786.76 v1(2030,1810) ; C16.2@2035,3288.5 2106.5,3288.5 v1(2150,3245) ; v1(2125,680) v1@2125,685 ; C24.2@2125.5,3131.94 2125.5,3083 v1(2127,3081.5) ; v1(2149,2029.5) 2151,2027.5 2151,1985.14 C32.2@2155.07,1981.07 ; v1(2225,2757.5) 2259,2791.5 C17.2@2280.5,2791.5 ; 2247,904.5 2257,914.5 2459,914.5 ; v1(2322,3081.5) 2322,3091.5 2333.5,3103 C29.2@2333.5,3131.94 2333.5,3165.01 2322,3176.5 U4.3@2322,3242.45 2322,3301.5 2325,3304.5 2580,3304.5 C31.2@2582,3306.5 ; v1(2330,2035) 2341.57,2046.57 U5.3@2341.57,2111.58 2341.57,2159.5 2354.95,2172.89 2568.41,2172.89 2589.8,2151.5 C38.2@2637,2151.5 2637.43,2151.07 2706.43,2151.07 2728.5,2129.01 C52.1@2787,2129.01 2813.5,2129.01 2872,2070.5 U8.1@2940,2070.5 ; v1(2340,1930) 2352,1942 2352,1980.01 C35.2@2353.06,1981.07 ; C19.2@2376.5,1545 2376.5,1601.5 v1(2385,1610) ; v1(2431,785.5) 2442,796.5 U7.3@2442,852.02 2442,897.5 2459,914.5 ; v1(2437,686.5) 2453.5,703 C44.2@2453.5,736.5 ; C46.2@2737,931.5 2687,931.5 2670,914.5 2459,914.5
  Bottom Layer w12: v1(1955,1565) 1957.34,1565 v1@1959.08,1563.26
  Bottom Layer w15: U11.2@1861.68,911.5 v1(1902,911.5) ; v1(1970,855) U13.2@2015.32,855 ; v1(2155,740) U12.2@2195.32,740
  Bottom Layer w20: J3.4@1274.08,1635.26 1287.57,1648.76 C57.2@1367.08,1648.76 ; v1(1370,405) C47.1@1458.5,405 ; R17.1@1380,775 C14.2@1448.5,775 ; C51.2@1391.5,3945 1405,3945 1445,3985 J2.1@1445,4040 ; v1@1545,2510 1545.8,2509.2 v1(1545.8,2502.49) ; v1(1622.08,1680.26) 1622.08,1681.26 1623.08,1682.26 1634.57,1670.77 C15.2@1634.57,1610.26 ; C13.2@1728.08,1820.26 v1(1728.08,1885.26) ; C53.2@1773.98,1264.85 1816.67,1264.85 1817.08,1265.26 v1(1825.08,1265.26) ; R28.1@1886.5,860 1965,860 v1(1970,855) ; v1(1935,800) R29.1@1993.5,800 ; C56.2@1968.08,1795.26 2015.26,1795.26 v1(2030,1810) ; v1(2125,680) 2130,685 R30.1@2173.5,685 ; v1@2224,2757.5 v1(2225,2757.5) ; v3(2694.5,3426.5) 2716,3426.5 2727,3437.5 R39.2@2727,3482.65
  Bottom Layer w40: v1(1185,1320) v1@1190,1320 ; C51.2@1391.5,3945 1391.5,3918.5 1645,3665 1645,3225 1635,3215
  Bottom Layer w50: 2597,3482.65 R39.2@2681,3482.65 ; R39.2@2695.14,3482.65 R39.2@2727,3482.65
  Bottom Layer w75: C25.2@2533.26,3671.5 2533.26,3546.39 2597,3482.65 2588.5,3474.15 v1@2588.5,1531.5
  other v1: 1270,1080 1340,1115 1220,1120 1285,1165 1245,1210 1380,1210 1335,1260 1375,1295 1903.08,1439.26 1725,1440 1810,1440 1646.08,1442.26 2812,1458 1811,1481 1902.08,1482.26 1724,1484 1648.08,1487.26 2813,1506 2597,1531.5 2812,1547 2462,1570.5 2597,1577.5 2600,1625 2482,1642.5 1185,1652 2425,1655 2340,1845 2150,1875 2340,1890 2150,1925 1185,2045 2140,2115 2190,2115 2165,2160 2143,2326.5 2140,2410 1185,2455 2145,2530 1625,2650 2143,2659.5 1915,2670 1965,2670 1625,2695 1580,2700 1865,2735 1915,2735 1965,2735 1493,2771 2832,2781.5 2595,2785 1865,2795 1915,2795 1965,2795 2832,2821.5 2595,2825 1496,2833 2360,2860 2595,2865 2832,2866.5 2364,2911.5 2280,2912.5 2318,2974.5 1690,2980 2115,3020 2320,3026.5 1645,3105 1695,3105 1700,3155 1645,3160 2322,3311.5
CSN: C33.2 R44.1 R49.1 | length 1969.2
  Top Layer w10: R49.1@1606.08,2196.26 1640.57,2161.76 1672.58,2161.76 1675.08,2164.26 v2(1675.08,2221.76) ; v2(2529,3355.5) 2600,3426.5 R44.1@2631.5,3426.5
  Bottom Layer w10: v2(1675.08,2221.76) 1694.08,2240.76 1694.08,2870.05 2183.53,3359.5 2525,3359.5 v2(2529,3355.5)
CSP: C33.1 R43.1 R54.1 | length 1911.4
  Top Layer w10: v2(1720,2230) 1734.08,2215.92 1734.08,2163.26 1735.57,2161.76 1738.57,2158.76 R54.1@1738.57,2090.76 ; v2(2500,3334.5) 2504,3330.5 2542,3330.5 2575,3363.5 R43.1@2631.5,3363.5
  Bottom Layer w10: v2(1720,2230) 1720,2870.52 2189.99,3340.5 2494,3340.5 v2(2500,3334.5)
EMT_U: C30.1 C37.1 C45.1 Q4.3 Q5.3 Q6.3 R38.1 R39.1 R43.2 R53.1 R64.1 U4.5 U5.5 U7.5 | length 2809.5
  Top Layer w20: U4.5@2422,3242.45 2422,3151.94 2442,3131.94 C30.1@2442,3121.94 2398.43,3121.94 2362,3085.5 2362,2964.5 2431.5,2895 2564.99,2895 R38.1@2600,2930.01 ; U5.5@2441.57,2111.58 2441.57,2056.94 2462,2036.5 2462,1976.5 C37.1@2461.57,1976.07 2426.07,1976.07 2380,1930 2380,1807.5 2424.5,1763.01 R53.1@2635,1763.01 ; U7.5@2542,852.02 2542,784.08 2557,769.08 C45.1@2557,726.5 2502,671.5 2502,582.5 2549.5,535 2694.99,535 R64.1@2709,549.01
  Top Layer w40: R38.1@2600,2930.01 2674.5,2930.01 2771,3026.5 Q4.3@2912,3026.5 ; R53.1@2635,1763.01 2703.5,1763.01 2785,1681.5 Q5.3@2912,1681.5 ; R64.1@2709,549.01 2766.5,549.01 2790,525.5 2906,525.5 Q6.3@2912,531.5
  Bottom Layer w20: v3(2694.5,3363.5) 2727,3331 R39.1@2727,3250.36
  Bottom Layer w50: R39.1@2722,3245.36 R39.1@2727,3250.36
EN: C49.2 R68.1 U4.4 U5.4 U7.4 | length 3844.5
  Top Layer w10: R68.1@1894.08,1789.76 C49.2@1894.08,1866.77 1895.57,1868.26 v2(1935.08,1868.26) 1971.08,1868.26 2045,1942.19 v2(2045,2070) 2045,2219.64 2019.08,2245.57 2019.08,3087.57 2109,3177.49 v2(2109,3209.5)
  Top Layer w20: U4.4@2372,3242.45 2372,3186.5 v2(2387,3171.5) ; v1(2387,2036.5) 2387,2046.5 2391.57,2051.07 U5.4@2391.57,2111.58 ; U7.4@2492,852.02 2492,796.5 v1(2507,781.5)
  Bottom Layer w10: v2(1935.08,1868.26) 2047.6,1868.26 2223,1692.86 2223,1312.21 2228,1307.21 2228,1060.5 v1(2507,781.5) ; v2(2045,2070) 2353.5,2070 v1(2387,2036.5) ; v2(2109,3209.5) 2349,3209.5 v2(2387,3171.5)
IDC_FB: C39.2 R52.2 U1.38 | length 186.7
  Top Layer w10: C39.2@1456.08,1735.77 R52.2@1521.08,1735.77 1521.08,1687.26 1537.76,1670.58 U1.38@1537.76,1620.93
IDC_OC: C42.2 R57.2 U1.33 | length 183.1
  Top Layer w10: R57.2@1588.28,1735.77 C42.2@1649.08,1735.77 1651.08,1733.77 1651.08,1679.26 1665.71,1664.63 U1.33@1665.71,1620.93 ; C42.2@1653.28,1735.77 C42.2@1653.71,1735.33
ISO_GND: C48.1 J5.1 U9.5 | length 281.1
  Top Layer w20: J5.1@1330,90 1330,185 v1(1360,215) 1409.49,215 U9.5@1410,215.51
  Bottom Layer w20: v1(1360,215) C48.1@1453.5,215
ISO_VCC: C48.2 J5.4 U9.8 | length 261.1
  Top Layer w20: U9.8@1560,215.51 1599.49,215.51 v1(1600,215) 1630,185 J5.4@1630,90
  Bottom Layer w20: C48.2@1516.5,215 v1(1600,215)
NetC1_2: C1.2 C3.1 L2.7 RT1.1
NetC3_2: C3.2 C6.1 D1.3 L2.9 | length 1804.3
  Bottom Layer w100: D1.3@611,2861 610,2860 610,2640 432.64,2462.64 C6.1@432.64,2340 610,2340 630,2320 630,1985 720,1895 C3.2@938.28,1895 938.28,1757.65 L2.9@806.85,1626.22
NetC4_1: C4.1 F1.1 L2.4 R1.2 RV1.2 | length 141.3
  Bottom Layer w20: C4.1@514.72,880 515,880.28 515,930 535,950 R1.2@597.91,950
NetC4_2: C4.2 J1.1 L2.2 R4.1 RV1.1 | length 219.3
  Bottom Layer w20: R4.1@917.09,945 922.09,950 1035.28,950 C4.2@1105.28,880
NetC12_1: C12.1 C13.1 C55.1 C56.1 C58.1 C59.1 R23.2 U1.1 U1.21 U1.31 | length 1727.8
  Top Layer w12: U1.1@1537.76,1329.59 1537.76,1255.58 C12.1@1548.08,1245.26 ; v1(1691.08,1681.26) 1691.08,1701.77 C58.1@1728.08,1738.77 1733.08,1733.77 1733.08,1678.26 1716.9,1662.08 U1.31@1716.9,1620.93 ; C55.1@1958.08,1723.77 1958.08,1675.26 1972.8,1660.54 U1.21@1972.8,1620.93 ; C55.1@1974.08,1721.26 2020.08,1721.26 v1(2026.08,1715.26)
  Top Layer w20: v1(1541.08,1048.76) 1542.57,1050.26 R23.2@1542.57,1098.76 C59.1@1542.57,1163.76 1547.08,1168.26 C12.1@1547.08,1245.26
  Bottom Layer w20: v1(1541.08,1048.76) 1541.08,1451.69 1691.08,1601.69 v1(1691.08,1681.26) 1728.08,1718.26 C13.1@1728.08,1740.26 1776.08,1740.26 1801.08,1715.26 C56.1@1968.08,1715.26 v1(2026.08,1715.26)
NetC24_1: C24.1 R32.2 U4.1 | length 199.8
  Top Layer w20: R32.2@2187,3058.43 2188.5,3059.93 C24.1@2188.5,3131.94 2187,3133.43 2187,3171.5 2222,3206.5 U4.1@2222,3242.45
